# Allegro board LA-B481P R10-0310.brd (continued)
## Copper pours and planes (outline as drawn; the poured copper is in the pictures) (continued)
LX_CHG on IN2 (solid shape): 158.22,169.31 158.22,168.32 158.07,168.17 157.05,168.17 156.95,168.27 156.95,169.29 157.1,169.44 158.09,169.44
LX_CHG on IN2 (solid shape): 166.42,175.77 166.42,175.03 166.3,174.9 164.39,174.9 164.21,175.08 164.21,175.74 164.34,175.87 166.32,175.87
MIC_IN on TOP (solid shape): 28.32,13.27 28.32,12.69 28.22,12.58 25.89,12.58 25.64,12.82 25.64,13.33 25.71,13.4 28.2,13.4
MIC_IN on TOP (solid shape): 39.2,21.66 40.68,21.66 40.75,21.6 40.75,21.49 40.69,21.44 39.7,21.44 39.69,21.43 39.59,21.43 39.58,21.41 39.35,21.41 38.89,20.95 36.76,20.95 36.68,21.03 36.68,21.61 36.76,21.69 39.18,21.69
MIC_IN on BOTTOM (solid shape): 16.92,16.34 16.92,14.81 16.67,14.55 15.78,14.55 15.65,14.68 15.65,16.36 15.76,16.47 16.79,16.47
MIC_IN on IN2 (solid shape): 16.88,15.02 16.88,13.64 16.61,13.37 15.91,13.37 15.69,13.59 15.69,15.15 15.77,15.23 16.67,15.23
MIC_IN on IN2 (solid shape): 39.01,21.45 39.01,20.89 37.58,19.47 37.35,19.47 36.74,20.08 36.74,20.23 38.29,21.78 38.68,21.78
MIC_IN on IN2 (solid shape): 28.1,13.4 28.1,12.76 27.82,12.48 24.77,12.48 24.64,12.61 24.64,13.38 24.78,13.52 27.97,13.52
MIC_IN_R on IN2 (solid shape): 16.21,9.29 16.21,7.19 16.08,7.06 15.4,7.06 15.01,7.44 15.01,9.27 15.12,9.37 16.13,9.37
MIC_IN_R on IN2 (solid shape): 15.09,20.95 15.09,18.92 15.01,18.84 14.13,18.84 13.82,19.15 13.82,21.02 13.92,21.12 14.92,21.12
MIC_IN_R on BOTTOM: 16.66,16.81 15.58,16.81 15.37,17.02 15.37,19.35 15.62,19.61 15.62,19.89 15.57,19.94 13.82,19.94 13.62,20.14 13.62,21 13.84,21.22 14.34,21.22 14.4,21.29 16.31,21.29 16.31,21.28 16.61,21.28 16.82,21.08 16.82,19.48 16.33,19 16.33,18.28 16.64,17.97 16.68,17.97 16.81,17.84 16.81,16.96
P2 on TOP: 143.13,161.44 144.78,161.44 145.28,160.94 145.28,160.2 145.27,160.19 145.27,159.95 145.14,159.81 143.46,159.81 143.28,159.99 143.28,160.63 143.03,160.88 143.03,161.34
P2 on BOTTOM: 136.1,164.62 144.2,164.62 144.35,164.46 144.35,160.83 143.79,160.27 136.1,160.27 135.84,160.53 135.84,164.36
P3 on BOTTOM: 145.22,156.36 145.88,157.02 147.17,157.02 147.22,157.07 147.22,158.65 147.4,158.82 147.81,158.82 147.98,158.65 147.98,157.1 148.03,157.05 149,157.05 149.15,157.2 149.15,160.55 148.85,160.86 144.73,160.86 143.92,160.04 142.14,160.04 142.13,160.06 140.91,160.06 140.74,159.89 140.74,155.88 140.9,155.73 143.36,155.73 144,156.36
PHASE1 on TOP: 156.09,124.05 158.5,124.05 159.13,123.42 159.13,119.2 159.03,119.1 153.85,119.1 153.55,119.4 153.55,121.66 153.65,121.77 154.66,121.77 155.07,122.17 155.07,123.01 154.66,123.42 151.49,123.42 151.45,123.45 151.45,124.39 151.49,124.43 155.71,124.43
PHASE1 on BOTTOM: 154.26,123.75 158.37,123.75 159.11,123.01 159.11,118.46 158.96,118.31 154.26,118.31 154.08,118.49 154.08,120.01 154.16,120.09 157.15,120.09 157.15,120.9 157.13,120.93 154.16,120.93 154.04,121.04 154.04,123.53
PHASE1 on BOTTOM: 158.95,129.92 159.02,129.85 160.04,129.85 160.24,130.06 160.24,131.32 160.61,131.69 161.46,131.69 161.54,131.77 161.54,131.93 161.49,131.99 160.46,131.99 160.04,131.57 159.26,131.57 158.95,131.26
PHASE1 on IN2: 160.28,131.19 160.28,130.25 159.87,129.84 158.7,129.84 158.51,130.04 158.51,130.79 159.03,131.32 160.15,131.32
PHASE1 on IN2: 154.99,122.97 156.11,122.97 156.25,123.11 156.25,123.49 155.71,124.03 155.71,124.29 155.53,124.47 155.05,124.47 155.04,124.46 154.7,124.46 154.59,124.36 154.59,123.59 154.94,123.24 154.94,123.02
PHASEG on BOTTOM (solid shape): 134.78,147.22 134.78,143.19 134.71,143.13 129.75,143.13 129.44,143.43 129.44,146.38 129.42,146.4 128.63,146.4 128.6,146.38 128.6,143.56 128.39,143.35 126.21,143.35 126.05,143.51 126.05,147.17 126.37,147.48 134.51,147.48
PHASEG on TOP: 140.87,141.2 140.95,141.12 140.95,140.13 140.87,140.05 138.36,140.05 138.1,139.8 136.07,139.8 135.41,139.14 132.34,139.14 130.81,140.66 130.81,144.96 131.09,145.24 134.6,145.24 134.8,145.03 134.8,144.12 134.85,144.07 134.85,143.36 137.01,141.2
PHASEG on BOTTOM: 161.48,134.1 160.66,134.1 159.68,135.08 158.47,135.08 158.27,135.28 158.27,135.81 158.4,135.94 159.85,135.94 161.53,134.26 161.53,134.15
PHASEG on IN2: 160.55,134.62 160.02,134.62 159.47,135.18 159.13,135.18 158.63,135.68 158.63,136.55 158.73,136.65 159.15,136.65 159.77,136.04 159.77,136.03 159.89,135.9 159.9,135.9 160.71,135.1 160.71,134.78
PHASEG on IN2: 137.52,139.96 137.52,140.78 137.65,140.9 139.5,140.9 139.91,140.5 139.91,140.04 139.68,139.81 137.67,139.81
RING2 on BOTTOM (solid shape): 18.81,16.37 18.81,14.81 18.56,14.55 17.54,14.55 17.42,14.68 17.42,16.34 17.53,16.46 18.72,16.46
RING2 on IN2 (solid shape): 19.03,14.99 19.03,13.69 18.29,12.96 17.59,12.96 17.35,13.2 17.35,15.02 17.57,15.23 18.79,15.23
RING2 on TOP: 40.7,21.84 40.76,21.89 40.76,21.99 40.7,22.05 39.74,22.05 39.43,22.36 39.42,22.36 39.21,22.57 39.2,22.57 39.18,22.59 36.72,22.59 36.71,22.58 36.71,22.02 36.78,21.94 38.97,21.94 39.07,21.84
RING2 on IN2: 36.59,23.16 38.57,23.16 38.8,22.93 38.8,22.3 38.55,22.05 36.54,22.05 36.34,22.25 36.34,22.88 36.59,23.14
RING2_R on TOP (solid shape): 15.17,8.53 15.17,7.11 14.82,6.77 14.16,6.77 14.13,6.73 13.72,6.73 13.54,6.91 13.54,7.16 13.97,7.59 13.97,8.66 14.02,8.71 14.99,8.71
RING2_R on TOP: 16.01,21 17.45,21 17.68,20.78 17.68,19.81 17.53,19.66 16.06,19.66 15.8,19.91 15.8,20.8
RING2_R on BOTTOM: 17.15,21.28 18.62,21.28 18.79,21.12 18.79,20.23 19.21,19.81 19.21,17.14 18.88,16.81 17.53,16.81 17.35,16.99 17.35,17.73 17.55,17.93 18.06,17.93 18.32,18.18 18.32,19.3 17.78,19.84 17.22,19.84 17.02,20.04 17.02,21.16
RTC_VOUT on TOP (solid shape): 66.45,42.11 66.45,41.04 66.02,40.61 66.02,39.32 65.97,39.27 65.87,39.27 65.79,39.34 65.79,40.41 64.85,41.35 64.42,41.35 64.29,41.48 64.29,42.09 64.39,42.19 66.37,42.19
SNB_3V on TOP: 133.44,20.88 133.44,21.69 133.56,21.82 134.77,21.82 135.28,22.33 135.28,22.55 135.37,22.65 136.99,22.65 137.04,22.6 137.04,21.31 136.45,20.72 133.59,20.72
SNB_5V on TOP: 121.98,22.45 122.23,22.19 123,22.19 123.12,22.06 123.12,21.18 123,21.05 120.84,21.05 120.83,21.05 120.5,21.05 120.27,21.29 120.27,22.27 120.27,22.27 120.27,22.32 120.4,22.45
SNB_CHG on BOTTOM (solid shape): 150.35,172.01 150.35,170.91 150.27,170.84 149.43,170.84 149.28,170.69 149.28,169.85 149.23,169.8 148.54,169.8 148.42,169.92 148.42,171.98 148.52,172.08 150.27,172.08
SPK_L1-_CONN on TOP (solid shape): 68.84,24.23 70.29,24.23 70.39,24.13 70.39,23.72 70.25,23.58 68.8,23.58 68.61,23.39 65,23.39 64.75,23.14 64.04,23.14 63.95,23.23 63.95,24.24 64.14,24.43 68.63,24.43
SPK_L2+_CONN on TOP (solid shape): 64.93,25.78 68.13,25.78 68.14,25.77 69.92,25.77 70.39,25.3 70.39,24.76 70.21,24.59 68.79,24.59 68.61,24.76 64.14,24.76 63.91,24.99 63.91,25.75 64.06,25.91 64.8,25.91
SPK_R1-_CONN on TOP (solid shape): 70.41,22.12 70.41,21.54 70.23,21.36 69.29,21.36 67.77,19.84 65.84,19.84 65.69,19.68 65.05,19.68 64.93,19.81 64.93,20.75 65.05,20.88 67.34,20.88 68.69,22.22 70.31,22.22
SPK_R2+_CONN on TOP (solid shape): 70.41,23.04 70.41,22.81 70.17,22.57 68.72,22.57 67.34,21.18 65.36,21.18 64.95,21.59 64.95,22.32 65.08,22.45 65.69,22.45 65.92,22.22 66.93,22.22 67.92,23.21 70.23,23.21
SW_1.35VP on BOTTOM (solid shape): 156.24,25.33 156.24,25.27 156.18,25.21 156.18,24.64 155.6,24.06 155.6,22.6 155.35,22.35 154.84,22.35 154.71,22.48 154.71,24.57 155.25,25.11 155.25,25.3 155.35,25.4 156.18,25.4
SW_1.35VP on BOTTOM (solid shape): 154.51,19.23 154.51,17.16 155.15,16.52 156.32,16.52 156.42,16.41 156.42,13.58 156.38,13.54 150.7,13.54 149.94,12.78 149.94,10.65 149.85,10.56 148.67,10.56 148.52,10.72 148.52,13.67 149.47,14.62 149.47,18.99 149.78,19.3 154.44,19.3
SW_1.35VP on IN2 (solid shape): 154.65,18.22 154.65,17.02 154.71,16.95 154.71,16.7 154.59,16.57 153.76,16.57 153.57,16.76 153.57,18.16 153.76,18.35 154.52,18.35
SW_1.35VP on IN2 (solid shape): 156.18,24.89 156.18,24.64 155.16,23.62 154.84,23.62 154.52,23.94 154.52,24.38 155.22,25.08 155.98,25.08
TL_ENVDD on BOTTOM (solid shape): 213.39,168.96 214.63,168.96 214.76,168.83 214.76,167.43 214.68,167.36 211.28,167.36 211.2,167.43 211.2,169.01 211.38,169.19 213.16,169.19
TL_ENVDD on BOTTOM: 201.37,164.44 201.76,164.44 202.01,164.18 203.41,164.18 203.51,164.29 203.51,164.59 203.41,164.69 202.57,164.69 202.24,165.02 202.24,165.83 202.09,165.99 201.37,165.99 201.2,165.81 201.2,164.62
TL_ENVDD on IN1: 202.39,163.93 204.55,166.09 216.56,166.09 218.32,164.34 219.41,164.34 219.71,164.64 219.71,166.37 216.23,169.85 203.48,169.85 202.29,168.65 199.95,168.65 199.32,168.02 199.32,164.39 199.77,163.93
UG_3V on TOP (solid shape): 131.6,18.03 131.6,17.78 131.22,17.4 131.22,16.89 131.16,16.83 130.39,16.83 130.27,16.95 130.27,17.52 131.05,18.31 131.32,18.31
UG_3V on TOP: 135.12,29.31 134.93,29.12 134.17,29.12 133.98,29.31 133.98,30.21 134.12,30.34 134.85,30.34 135.12,30.07
UG_3V on IN2: 131.07,17.08 130.47,17.08 130.33,17.22 130.33,17.49 131.89,19.05 132.06,19.05 132.49,18.62 132.49,18.5
UG_3V on IN2: 134.96,30.7 135.09,30.57 135.09,29.18 134.9,28.99 134.11,28.99 133.86,29.23 133.86,30.53 134.03,30.7
UG_5V on TOP (solid shape): 122.96,27.53 123.63,27.53 123.75,27.4 123.75,27.15 123.56,26.96 122.74,26.96 122.48,26.71 121.94,26.71 121.72,26.92 121.72,27.63 121.94,27.85 122.65,27.85
UG_5V on TOP: 126.88,17.61 127,17.74 127.83,17.74 128.02,17.55 128.02,17.17 128.15,17.04 128.15,16.86 128.07,16.79 127.23,16.79 126.88,17.14
UG_5V on IN2: 126.2,17.02 126.04,17.18 126.04,17.85 126.22,18.03 126.77,18.03 127.16,17.65 128.04,17.65 128.11,17.59 128.11,17.27 127.85,17.02
UG_5V on IN2: 121.73,26.77 121.73,27.85 121.86,27.98 122.88,27.98 123.13,27.72 123.13,26.2 123,26.07 122.43,26.07
UGATE1 on TOP (solid shape): 157.13,126.18 157.13,124.34 157.05,124.25 156.16,124.25 156.01,124.41 156.01,126.11 156.14,126.24 157.08,126.24
UGATE1 on BOTTOM: 161.5,131.56 160.66,131.56 160.44,131.34 160.44,130.09 160.54,129.99 161.12,129.99 161.19,130.06 161.19,131.07 161.53,131.42 161.53,131.52
UGATE1 on IN2: 156.07,124.14 156.07,124.55 156.23,124.71 157.68,124.71 157.93,124.46 157.93,123.89 157.81,123.76 156.45,123.76
UGATE1 on IN2: 160.73,131.21 160.52,131 160.52,129.18 160.8,128.9 161.17,128.9 161.47,129.21 161.47,131.04 161.29,131.21
UGATE1-1 on TOP (solid shape): 155.69,126.17 155.69,125.3 155.6,125.21 154.85,125.21 154.64,125.42 153.57,125.42 153.5,125.5 153.5,126.16 153.57,126.24 155.63,126.24
UGATEG1 on TOP (solid shape): 142.78,141.83 142.78,140.79 142.65,140.66 141.38,140.66 141.13,140.92 141.13,141.83 141.2,141.91 142.7,141.91
UGATEG1 on BOTTOM: 161.82,135.25 161.82,134.46 161.76,134.41 161.59,134.41 161.17,134.83 160.43,135.57 160.43,135.77 160.76,136.1 160.97,136.1
UGATEG1 on IN2: 161.47,134.95 161.04,134.95 159.72,136.26 159.72,136.68 160.35,137.31 160.71,137.31 161.8,136.22 161.8,135.28
UGATEG1 on IN2: 141,140.97 141,141.68 141.28,141.96 142.8,141.96 143.03,141.73 143.03,140.21 142.89,140.07 142.85,140.1 141.86,140.1
UGATEG1-1 on TOP: 140.31,142.19 140.31,142.8 140.57,143.05 142.6,143.05 142.7,142.95 142.7,142.16 142.68,142.14 140.36,142.14
VGA_V1P35_S3_F1 on BOTTOM: 106.58,136.12 108.89,133.81 108.89,132.64 109.1,132.43 109.1,132.13 108.92,131.95 108.69,131.95 107.74,132.9 106.87,132.9 104.14,135.63 104.14,136.26 105.06,137.17 105.78,137.17 106.58,136.37
N17188574 on BOTTOM (solid shape): 62.39,88.86 62.39,85.98 62.31,85.9 62.31,85.8 62.14,85.63 60.53,85.63 59.72,86.45 59.72,88.31 60.46,89.05 62.2,89.05
N17227658 on BOTTOM (solid shape): 168.74,152.79 168.74,151.01 169.05,150.7 171.59,150.7 171.72,150.57 171.72,148.35 171.59,148.22 166.01,148.22 165.75,148.47 165.75,148.92 165.81,148.98 166.26,148.98 166.32,149.05 166.32,149.49 166.32,149.5 166.32,149.56 166.27,149.6 165.79,149.6 165.75,149.64 165.75,149.74 165.81,149.81 166.26,149.81 166.32,149.87 166.32,150.42 166.25,150.49 165.85,150.49 165.75,150.59 165.75,152.6 166.13,152.98 168.55,152.98
N17256593 on BOTTOM (solid shape): 156.82,12.6 156.82,10.97 156.49,10.64 151.41,10.64 151.34,10.71 151.34,12.45 151.6,12.7 156.72,12.7
N17322935 on TOP: 131.07,172.26 132.26,172.26 132.39,172.13 132.39,171.5 132.31,171.42 131.35,171.42 130.43,170.51 130.43,169.97 130.31,169.85 127.66,169.85 127.51,170 127.51,171.19 127.89,171.57 130.38,171.57
N17344663 on TOP (solid shape): 134.14,184.07 134.14,183.87 134.17,183.84 134.17,183.18 134.19,183.16 134.67,183.16 134.7,183.13 134.7,182.73 134.67,182.7 134.17,182.7 134.14,182.67 134.14,181.99 134.19,181.94 134.67,181.94 134.7,181.91 134.7,181.53 134.67,181.51 134.19,181.51 134.14,181.46 134.14,180.62 134.12,180.59 132.9,180.59 132.72,180.77 132.67,180.77 132.34,181.1 132.34,181.73 131.98,182.09 131.98,184 132.21,184.22 133.99,184.22
N17344663 on BOTTOM: 127.94,184.2 134.62,184.2 135.08,183.74 135.08,177.85 135.49,177.44 138.13,177.44 138.48,177.09 138.48,173.78 138.15,173.45 127.92,173.45 127.49,173.89 127.49,183.74
N19142937 on TOP: 146.49,157.4 146.79,157.71 146.79,162.08 145.85,163.02 145.42,163.02 145.22,162.81 145.22,161.36 145.57,161.01 145.57,159.97 145.24,159.64 142.42,159.64 141.96,159.18 140.01,159.18 139.93,159.26 137.7,159.26 137.57,159.13 137.57,158.42 137.9,158.09 139.42,158.09 140.11,157.4
N19142937 on BOTTOM: 146,161.66 146,163.45 145.88,163.57 144.86,163.57 144.64,163.36 144.64,161.67 144.8,161.51 145.85,161.51
N19142937 on BOTTOM: 139.91,160.07 140.06,159.92 140.06,158.85 139.88,158.67 137.67,158.67 137.62,158.72 137.62,159.97 137.72,160.07
N23316235 on BOTTOM: 43.69,75.54 45.09,75.54 45.16,75.61 45.47,75.61 45.52,75.56 45.52,75.05 45.55,75.03 45.95,75.03 45.98,75.05 45.98,75.56 46.03,75.61 46.79,75.61 46.92,75.74 46.92,76.05 47.1,76.22 47.98,76.22 48.21,75.99 48.21,73.96 47.81,73.56 43.72,73.56 43.41,73.86 43.41,75.26
N24334655 on BOTTOM (solid shape): 172.86,115.56 172.86,114.67 172.93,114.6 173.41,114.6 173.43,114.58 173.43,114.42 173.41,114.4 172.88,114.4 172.85,114.37 172.85,112.66 172.41,112.22 170.12,112.22 169.93,112.41 169.93,115.8 170.07,115.94 172.48,115.94
N24559749 on BOTTOM (solid shape): 53.9,90.32 53.9,88.42 54.46,88.42 54.46,88.26 53.9,88.26 53.9,87.86 53.88,87.83 52.18,87.83 51.95,88.06 51.95,89.51 51.82,89.63 51.64,89.63 51.41,89.86 51.41,90.47 51.64,90.7 53.52,90.7
N24654163 on TOP (solid shape): 134.83,17.47 134.83,15.39 134.75,15.31 134.17,15.31 134.06,15.42 134.06,17.47 134.17,17.57 134.73,17.57
N24654248 on TOP: 123.7,17.55 124.36,17.55 124.39,17.52 124.39,15.34 124.36,15.31 123.7,15.31 123.65,15.36 123.65,17.5
N29841026 on TOP (solid shape): 134.45,161.57 134.45,158.82 134.32,158.7 132.59,158.7 132.31,158.98 132.31,161.62 132.44,161.75 134.27,161.75
N100768097 on TOP: 152.89,121.74 152.89,120.95 152.81,120.88 151.39,120.88 151.21,121.05 151.21,121.77 151.29,121.84 152.78,121.84
N100768278 on TOP: 136.4,139.65 137.49,139.65 137.54,139.6 137.54,137.97 137.49,137.92 136.48,137.92 136.33,138.07 136.33,139.57
N100768460 on BOTTOM: 159.03,129.36 159.79,129.36 159.92,129.23 159.92,127.2 159.79,127.07 159.03,127.07 158.91,127.2 158.91,129.23
N100768507 on BOTTOM: 158.58,138.73 159.46,138.73 159.67,138.53 159.67,136.73 159.44,136.5 158.4,136.5 158.35,136.55 158.35,138.5

Small or netless copper shapes (teardrops, artwork), in the pictures only: 20 on TOP, 186 on BOTTOM

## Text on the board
Ref Des/Silkscreen Bottom: H10 | H6 | Only | Support | DDR3L | H18
User.Comments: LA-B481P | 2015-03-10 | 2014-03-10 | Juce | ZBW00 | 1.0(A00) | gnd | gnda | +5valw | +1.8vs | +3vs | +1.8valw | +1.0vs | +soc_vnn | +soc_vcc | +1.5vs | batt+
COMPVAL_TYPE_TOP: FIGURE | SIZE | 8.0 | 10.0 | 12.0 | 22.0 | 24.0 | 28.0 | 31.0 | 35.0 | 36.0 | 39.0 | 91.0 | 110.0 | 130.0 | 146.0 | 43.0 | 47.0 | 63.0 | 71.0 | 28.0x16.0 | 47.0x24.0 | 63.0x28.0 | 71.0x20.0 | 79.0x31.0 | 87.0x43.0 | 91.0x35.0 | 94.0x39.0 | 110.0x39.0 | 146.0x126.0 | DRILL CHART: TOP to BOTTOM | ALL UNITS ARE IN MILS | PLATED | NON-PLATED | QTY | 2170 | 1353 | 1 | 19 | 6 | 7 | 22 | 8 | 12 | 9 | 2 | 4 | 3 | 26
User.22: 103.70 | 111.86 | 174.00 | 142.15 | 82.65 | 88.30 | 55.01 | 49.75 | 39.66 | 56.34 | 38.00 | 1.25 | 24.93
User.23: 14.60 | 1.85 | 3.45 | 27.00 | 44.60 | 62.20 | 217.12 | 214.88 | 213.00 | 212.51 | 209.10 | 179.85 | 81.47 | 155.58 | 158.85 | 131.90 | 90.60 | 103.25 | 69.68 | 105.45 | 145.77 | 13.13 | 17.00 | 0.00
User.24: 8.50 | 149.90 | 114.20 | 104.50 | 98.76 | 67.00 | 33.20 | 203.30 | 198.28 | 194.00 | 144.40 | 116.00 | 97.60 | 84.00 | 71.90 | 61.00 | 29.40 | 21.10 | 76.50 | 89.50 | 89.55 | 115.85 | 124.16 | 139.60 | 163.50 | 182.60 | 0.00 | 2.60
User.25: {\Fgdt;n}\Ftxt;2.80 | {\Fgdt;n}\Ftxt;3.30 | {\Fgdt;n}\Ftxt;9.00 | {\Fgdt;n}\Ftxt;3.70 | {\Fgdt;n}\Ftxt;8.00 | {\Fgdt;n}\Ftxt;3.20 | {\Fgdt;n}\Ftxt;2.30 | {\Fgdt;n}\Ftxt;6.00 | {\Fgdt;n}\Ftxt;5.80
User.30: 0.00
User.40: 14.60 | 1.85 | 3.45 | 27.00 | 44.60 | 62.20 | 217.12 | 214.88 | 213.00 | 212.51 | 209.10 | 179.85 | 81.47 | 155.58 | 158.85 | 131.90 | 90.60 | 103.25 | 69.68 | 105.45 | 13.13 | 17.00 | 0.00
User.41: 103.70 | 111.86 | 174.00 | 142.15 | 82.65 | 88.30 | 55.01 | 49.75 | 39.66 | 56.34 | 38.00 | 1.25 | 24.93
